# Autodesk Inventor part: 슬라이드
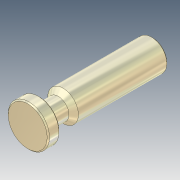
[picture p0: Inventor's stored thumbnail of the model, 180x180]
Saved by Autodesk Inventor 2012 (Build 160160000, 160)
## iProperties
Company: 한국ATC센터
Created: 2014-11
Part Number: 슬라이드
Document SubType Name: Modeling
Designer: KYOUNG IL JANG
Density: 7.86 g/cm^3
Material: 강, 연강
Mass: 436.103 g
Surface Area: 105.764 cm^2
Volume: 55.4838 cm^3
Author: KYOUNG IL JANG
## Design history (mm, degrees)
sketch "스케치1"
  geometry: L1 (19, 106.5)-(-19, 106.5) reference; L2 (0, 106.5)-(0, 212.5); L3 (0, 212.5)-(-13, 212.5); L4 (-13, 212.5)-(-13, 136.5); L5 (-9, 116.5)-(-17.5, 116.5); L6 (-17.5, 116.5)-(-17.5, 106.5); L7 (-17.5, 106.5)-(0, 106.5); L8 (-9, 116.5)-(-9, 132.5); L9 (-9, 132.5)-(-13, 136.5); 1 further point
  constraints: 18 end point, 3 perpendicular, 1 collinear, 1 horizontal, 1 midpoint, 1 parallel, 2 other
  dimensions: "d0" = 10 distance between parallel lines of L5 L7; "d1" = 35 diameter of L6 L2; "d2" = 106 distance of L2.start L2.end; "d3" = 135 deg angle of L9 L4; "d4" = 18 diameter of L8 L2; "d5" = 30 distance from line of L4.end L7; "d11" = 26 diameter of L4 L2
revolve "회전1" sketch "스케치1" stored, may be unused: angle "d6" = 90 deg
chamfer "모따기1" distance "d7" = 1; stored, may be unused: second distance "d8" = 2, angle "d9" = 45 deg
fillet "모깎기1" dims "d10" = 2
node "솔리드1"
